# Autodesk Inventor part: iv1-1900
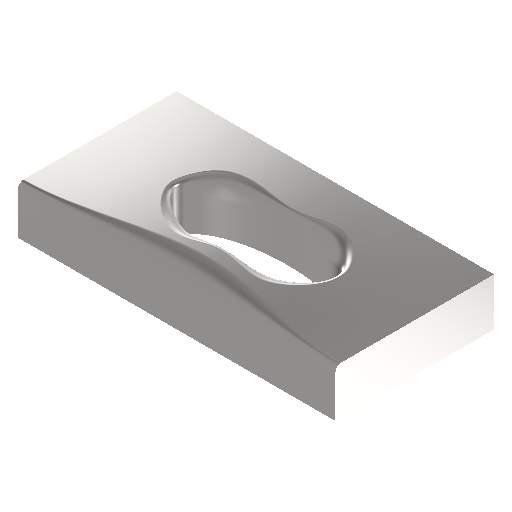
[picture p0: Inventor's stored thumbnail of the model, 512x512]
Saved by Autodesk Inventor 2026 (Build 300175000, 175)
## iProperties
Created: 2004-09
Part Number: iv1-1900
Document SubType Name: Modeling
Designer: Lars Bertram Pedersen
Manufacturer: Standard
Standards Organization: Custom
Material: Steel, Mild
Density: 7.85 g/cm^3
Appearance: Semi-Polished
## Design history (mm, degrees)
sketch "Sketch1" dims "d3" = 20, "d4" = 8
  geometry: L1 (0, 0)-(80, 0); L2 (80, 0)-(80, 40); L3 (80, 40)-(0, 40); L4 (0, 40)-(0, 0); 2 further points; 1 other entity
  constraints: 8 end point, 2 horizontal, 2 parallel, 1 coincident, 1 perpendicular, 2 other
  dimensions: "d1" = 40 distance of L3.end L1.start; "d2" = 40 distance from line of point (40, 20) L4; "d5" = 20 distance from line of point (40, 20) L1; "d6" = 40 distance from line of point (40, 20) L2
extrude "Extrusion1" new body sketch "Sketch1" distance "d7" = 12; taper "d8" = 0 deg
fillet "Fillet1" dims "d9" = 1.5, "d10" = 1.5, "d11" = 8, "d12" = 5
fillet "Fillet2" dims "d13" = 8, "d14" = 8, "d15" = 1, "d16" = 0, "d17" = 1, "d18" = 2.5, "d19" = 1, "d20" = 5, "d21" = 1, "d22" = 7.5, "d23" = 4, "d24" = 1.519, "d25" = 4, "d26" = 3.272, "d27" = 4, "d28" = 6.294, "d29" = 4, "d30" = 8.438
body "Solid1"
